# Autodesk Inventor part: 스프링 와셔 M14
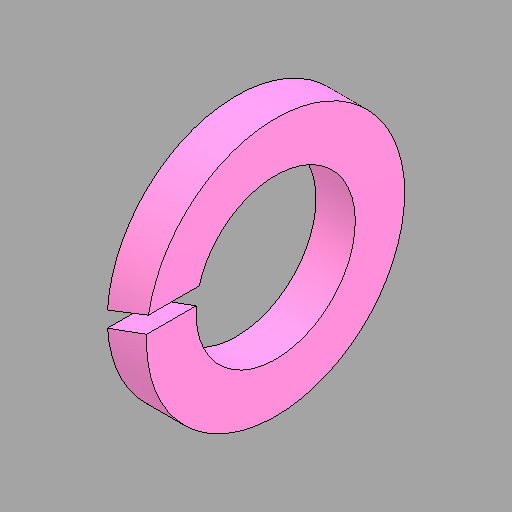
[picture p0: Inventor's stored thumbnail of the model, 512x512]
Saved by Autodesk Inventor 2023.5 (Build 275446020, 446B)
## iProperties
Created: 2025-07
Part Number: 스프링 와셔 M14
Material: 강철, 연강
Description: 스프링 잠금 와셔
Document SubType Name: Modeling
Designer: 1강의실14
Density: 7.85 g/cm^3
Appearance: 기본값
Author: jhkim
Sending System: Autodesk Inventor 2026
Preprocessor: ST-DEVELOPER v20.1
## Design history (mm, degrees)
feature "Solid1"
node "솔리드1"
